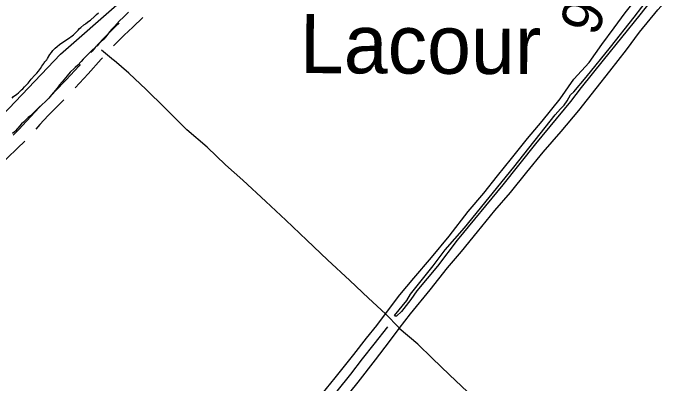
# Model space of a CAD drawing. Extents: x 3161514 to 3199414, y 831166 to 856601.
# Drawn here: x 3188637 to 3190239, y 847621 to 848532 of the extents above; entities that cross this region are included whole.
import ezdxf

# ---------------------------------------------------------------- set-up
doc = ezdxf.new("R2010")
doc.units = 0
for name, color, linetype in [('V-ROAD-CNTR', 7, 'Continuous'), ('V-SITE-VEGE', 7, 'Continuous'), ('V-SURV-IDEN', 7, 'Continuous'), ('V-TOPO-GNAM-IDEN', 7, 'Continuous'), ('V-TOPO-SHOR', 7, 'Continuous')]:
    doc.layers.add(name, color=color, linetype=linetype)

msp = doc.modelspace()

# ---------------------------------------------------------------- linework, layer by layer
at = {"layer": 'V-ROAD-CNTR'}
for points in [[(3188955.3, 848520.9), (3188931.4, 848497), (3188920.4, 848487.2), (3188910, 848477.6), (3188899.8, 848467.8), (3188889.8, 848457.9), (3188883.4, 848451.4)], [(3188897.6, 848506.9), (3188889.5, 848499.5), (3188878.9, 848489.3), (3188868.5, 848479), (3188858.2, 848468.5), (3188848.2, 848457.8), (3188838.3, 848447), (3188830.9, 848438.6), (3188827.9, 848435.3)], [(3188856.3, 848422), (3188853.4, 848418.7), (3188821, 848382.3), (3188789.3, 848347.8)], [(3188801.4, 848405.3), (3188798.8, 848402.4), (3188766, 848366.8), (3188740.3, 848339.6), (3188740.3, 848339.9), (3188733.2, 848332.8)], [(3188761.7, 848318.9), (3188744.4, 848301.6), (3188723.3, 848279.9), (3188702.6, 848257.8), (3188692.5, 848246.7)], [(3188705.2, 848304.3), (3188701.6, 848300.6), (3188680.5, 848278.1), (3188659.9, 848255.3), (3188651.9, 848246.3), (3188636.6, 848231.6)], [(3188665.2, 848217.5), (3188647.4, 848200.3), (3188622.1, 848175.1), (3188597.3, 848149.4), (3188594.7, 848146.6)]]:
    msp.add_lwpolyline(points, dxfattribs=at)
at = {"layer": 'V-SITE-VEGE'}
msp.add_line((3188853.8, 848441.7), (3188883.9, 848416.8), dxfattribs=at)
for points in [[(3189613.5, 847793.1), (3189661.6, 847851.9), (3189704.9, 847905.8), (3189739.2, 847946.3), (3189778.3, 847994.3), (3189821.2, 848046.6), (3189859.1, 848090.9), (3189899.7, 848141), (3189940, 848189.9), (3189983.6, 848241.3), (3190027.8, 848292.4), (3190070, 848346.2), (3190103.9, 848389.4), (3190144.3, 848441.9), (3190176.5, 848485.1), (3190221.6, 848539.5), (3190256, 848578.6), (3190292.9, 848624.3), (3190327.7, 848666.2), (3190379.4, 848727.7), (3190420.7, 848777.3), (3190460.4, 848824.9), (3190485.5, 848852.3)], [(3189937.5, 848266.5), (3189981.2, 848321), (3190015.1, 848369.7), (3190052.6, 848410.3), (3190084.1, 848454.9), (3190114.3, 848495.8), (3190141, 848532.1), (3190177.7, 848578.7)], [(3188920.4, 848533.8), (3188913.9, 848527.5), (3188911.1, 848525.1), (3188907.9, 848521.9), (3188898.4, 848513), (3188886.3, 848499.1), (3188879.8, 848492.1), (3188874, 848486.2), (3188869.4, 848480.4), (3188864.1, 848473.1), (3188859.7, 848468.2), (3188851.1, 848459.8), (3188847.6, 848456), (3188843, 848451.8), (3188840.2, 848448.8), (3188829.5, 848439.1), (3188827.2, 848436.3), (3188825.1, 848434.7), (3188822.1, 848432.1), (3188820.3, 848430.2), (3188816.3, 848426), (3188809.1, 848418.7), (3188803.8, 848412.9), (3188795.7, 848403.5), (3188789.7, 848398.1), (3188785.7, 848395.1), (3188778.3, 848388.5), (3188776.7, 848386.9), (3188769.8, 848377.3), (3188757.2, 848363), (3188751.2, 848355.2), (3188745, 848347.5), (3188730.9, 848331.1), (3188724.6, 848322.9), (3188723, 848321.1), (3188719.3, 848317.8), (3188715.8, 848314), (3188708.4, 848307), (3188700.3, 848299.9), (3188694.2, 848294.1), (3188682.2, 848281.9), (3188679.4, 848279.5), (3188674.1, 848275.3), (3188669.9, 848271.6), (3188665.2, 848267.1), (3188662.2, 848264.1), (3188657.6, 848259.6), (3188648.1, 848249.3), (3188646.5, 848247.7), (3188642.5, 848242.7), (3188639.8, 848239.9), (3188635.1, 848236.2)], [(3188732.6, 848437.4), (3188734.4, 848439.8), (3188740, 848445.6), (3188744.9, 848449.8), (3188751.1, 848454.8), (3188763.9, 848463.7), (3188773, 848469.4), (3188782.3, 848475.7), (3188785.5, 848478.5), (3188793.4, 848487), (3188796.4, 848490.2), (3188799.6, 848494), (3188802.9, 848496.8), (3188810.5, 848502.9), (3188813.6, 848505), (3188815.9, 848506.4), (3188823.3, 848511.8), (3188826.6, 848514.6), (3188836.5, 848523.3), (3188841.9, 848528.3), (3188846.3, 848532.7)], [(3188634.2, 848322.6), (3188637.6, 848326.9), (3188645.8, 848333), (3188649.9, 848335.8), (3188651.6, 848337.7), (3188657.6, 848343.5), (3188660.6, 848346.1), (3188665, 848350.6), (3188673.8, 848359.7), (3188681.5, 848369.1), (3188690.3, 848379.4), (3188694.9, 848384.1), (3188699.5, 848389), (3188703.9, 848395.8), (3188707.1, 848401.8), (3188712.2, 848407.7), (3188713.2, 848409.8), (3188714.8, 848412.1), (3188718.5, 848415.9), (3188719.2, 848417.1), (3188719.6, 848417.3), (3188721.3, 848420.3), (3188727.3, 848430.2), (3188731.2, 848435.3), (3188732.6, 848437.4)], [(3189552.2, 847793.1), (3189510.6, 847831), (3189464.8, 847874.8), (3189409.9, 847925.7), (3189359, 847973.7), (3189306.8, 848022.8), (3189257.8, 848068.6), (3189201.5, 848121.2), (3189159.1, 848158.9), (3189114.1, 848202.5), (3189063.4, 848245.1), (3189009.5, 848299), (3188963.7, 848344.4), (3188921.4, 848384.1), (3188885.4, 848415.6), (3188883.9, 848416.8)], [(3189552.2, 847793.1), (3189587.4, 847839.6), (3189622.2, 847880.3), (3189665.4, 847931.1), (3189709, 847983.5), (3189755.7, 848044.6), (3189794.1, 848089.7), (3189827.6, 848131.6), (3189861.6, 848174.7), (3189901.3, 848223.6), (3189937.5, 848266.5)], [(3189271, 847360.2), (3189316.5, 847417.6), (3189362.7, 847475.3), (3189401.3, 847523.1), (3189444.1, 847574.2), (3189484.6, 847625.1), (3189527.3, 847679.8), (3189562.1, 847724.7), (3189586, 847756.9), (3189613.5, 847793.1)], [(3189428.7, 847635.5), (3189474.7, 847693), (3189505.7, 847733), (3189531.1, 847763.8), (3189552.2, 847793.1), (3189586, 847758.3)], [(3189586, 847756.9), (3189586, 847758.3), (3189586, 847756.9)], [(3189990.5, 847380.6), (3189943.4, 847423.8), (3189905.2, 847459), (3189867.8, 847493.4), (3189828, 847531.9), (3189794.3, 847562.1), (3189754.1, 847601.2), (3189709.5, 847642.6), (3189666.8, 847683.8), (3189631.8, 847718.3), (3189586, 847756.9)], [(3188881, 846957.7), (3188916.5, 847000.9), (3188946.4, 847041.6), (3188972.8, 847072.6), (3189005.7, 847110.4), (3189040.6, 847152), (3189070.5, 847189), (3189102.8, 847228.7), (3189136.1, 847273.5), (3189165.6, 847309.8), (3189199.1, 847352.5), (3189232.8, 847393.5), (3189264.2, 847429.4), (3189292.1, 847466.7), (3189326.3, 847511.2), (3189361.7, 847558), (3189396.7, 847596.3), (3189428.7, 847635.5)]]:
    msp.add_lwpolyline(points, dxfattribs=at)
at = {"layer": 'V-TOPO-SHOR'}
for points in [[(3187811.7, 847458.9), (3187989.6, 847610.7), (3188530.7, 848197.7), (3188753.4, 848431.1), (3189043.4, 848685.7), (3189351, 849021.6)], [(3189574.3, 847789), (3189604.8, 847825.8), (3189613.8, 847841), (3189639.7, 847874), (3189669.1, 847910.5), (3189698.8, 847950.1), (3189746, 848004.4), (3189868, 848153.6), (3189969.4, 848281.9), (3189982.4, 848296.2), (3189991.2, 848305.4), (3189998.8, 848316.1), (3190007.3, 848330.6), (3190014.8, 848338.1), (3190045.3, 848374.4), (3190105, 848448.4), (3190163.8, 848522.2), (3190220.1, 848596.4), (3190261.7, 848649.3)], [(3190247.7, 848617.3), (3190177.6, 848527.4), (3190087.5, 848416.4), (3190033.1, 848349.2), (3190007, 848315), (3189921.3, 848210.6), (3189840.8, 848109.9), (3189728.7, 847973.6), (3189680.1, 847910.1), (3189629.6, 847849), (3189614.4, 847828.2), (3189591.5, 847798.7), (3189579.6, 847786.9), (3189576.1, 847786.7), (3189574.3, 847789)], [(3189172.9, 847280.2), (3189212, 847329.5), (3189248.4, 847376.5), (3189295.4, 847432.3), (3189335.8, 847479.7), (3189371.8, 847526.1), (3189403.8, 847563.7), (3189433.6, 847602.8), (3189466.9, 847644.3), (3189495.7, 847682.1), (3189524.7, 847717.9), (3189557.6, 847760.7)]]:
    msp.add_lwpolyline(points, dxfattribs=at)

# ---------------------------------------------------------------- texts
at = {"layer": 'V-SURV-IDEN'}
msp.add_text('906+86.8', height=100, rotation=69.7063, dxfattribs=at).set_placement((3190071, 848471.7))
at = {"layer": 'V-TOPO-GNAM-IDEN'}
msp.add_text('Lacour', height=145, rotation=359.7335, dxfattribs=at).set_placement((3189341.5, 848384.5))

doc.saveas('drawing.dxf')
